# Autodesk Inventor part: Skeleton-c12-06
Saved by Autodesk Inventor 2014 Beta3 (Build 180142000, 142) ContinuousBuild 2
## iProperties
Created: 2011-01
Part Number: Skeleton-c12-06
Material: Generic
Document SubType Name: Modeling
Designer: Thom Tremblay
Density: 1 g/cm^3
Appearance: Generic
_SkeletonDoc: Frame Skeleton File
_Version: 15.0.0
Author: Thom Tremblay
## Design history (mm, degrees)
sketch "Reference Skeleton"
  geometry: L1 through (404.523, 1164.395) direction (1, 0); L2 through (325.691, 1070.446) direction (1, 0); 34 other entities
  constraints: 10 horizontal
